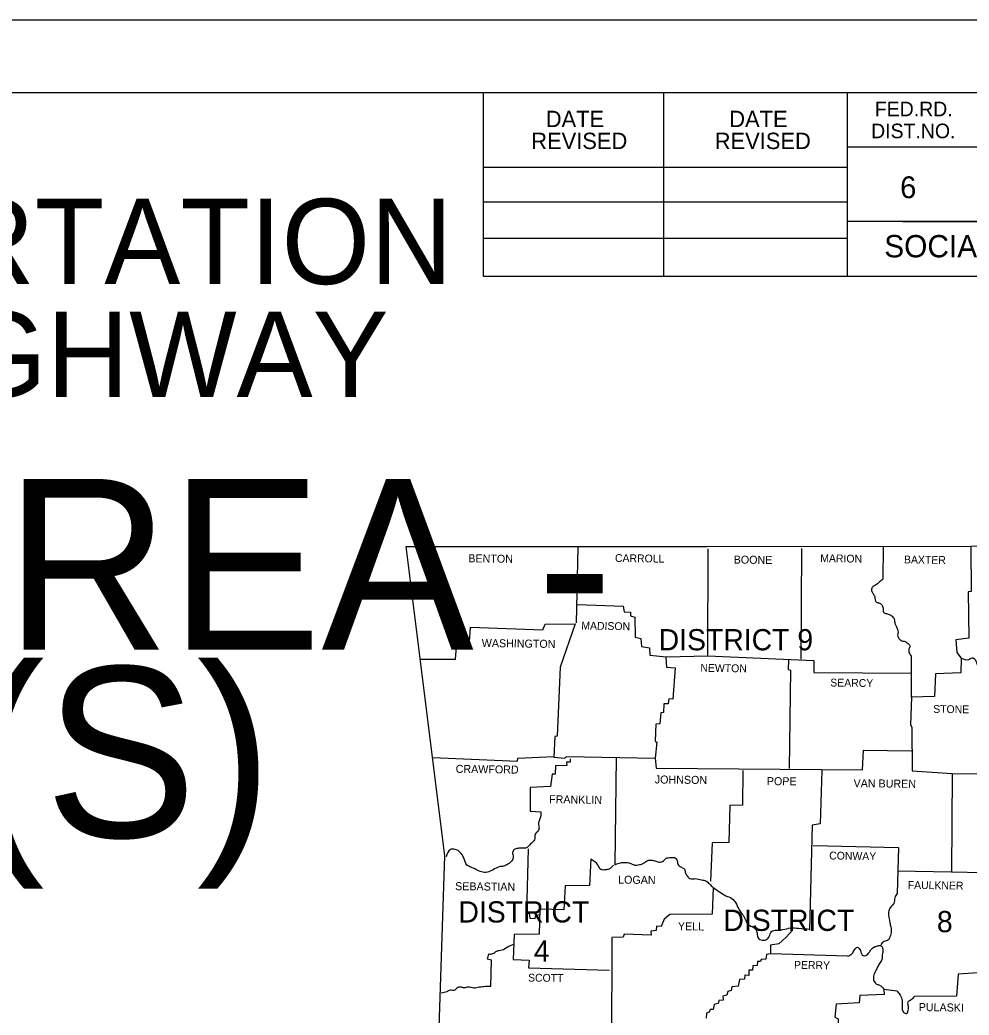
# Model space of a CAD drawing. Extents: x 22866 to 28196, y 1324810 to 1328105.
# Drawn here: x 26170 to 26680, y 1327007 to 1327542 of the extents above; entities that cross this region are included whole.
import ezdxf

# ---------------------------------------------------------------- set-up
doc = ezdxf.new("R2010")
doc.units = 0
for name, color, linetype in [('R_Border', 7, 'Continuous'), ('R_Border Notes', 7, 'Continuous'), ('R_Draft', 7, 'Continuous'), ('R_No Plot', 7, 'Continuous')]:
    doc.layers.add(name, color=color, linetype=linetype)

msp = doc.modelspace()

# ---------------------------------------------------------------- linework, layer by layer
at = {"layer": 'R_Border'}
for p, q in [((23883.86, 1327502.95), (27045.59, 1327502.95)), ((26419.2, 1327404.15), (26419.2, 1327502.95)), ((26516, 1327404.15), (26516, 1327502.95)), ((26614.6, 1327502.95), (26614.6, 1327404.15)), ((27045.59, 1327473.55), (26614.6, 1327473.55)), ((26419.2, 1327462.75), (26614.6, 1327462.75)), ((26419.2, 1327444.15), (26614.6, 1327444.15)), ((27045.59, 1327433.55), (26614.6, 1327433.55)), ((26644.2, 1327433.55), (27045.59, 1327433.55)), ((26419.2, 1327424.75), (26614.6, 1327424.75)), ((27045.59, 1327404.15), (26419.2, 1327404.15))]:
    msp.add_line(p, q, dxfattribs=at)
at = {"layer": 'R_Draft'}
for points in [[(26377.45, 1327259.08), (26539.15, 1327258.98), (26681.05, 1327259.28), (26848.45, 1327261.88), (26926.05, 1327263.68)], [(26377.45, 1327259.08), (26398.15, 1327092.88), (26389.15, 1326821.58)], [(26469.75, 1327258.48), (26468.85, 1327217.98)], [(26469.55, 1327227.88), (26494.15, 1327227.08), (26494.75, 1327223.88), (26498.15, 1327223.78), (26498.05, 1327221.78), (26500.45, 1327221.18), (26500.65, 1327210.28), (26503.75, 1327209.58), (26503.95, 1327205.28), (26508.35, 1327204.68), (26508.55, 1327200.68), (26517.25, 1327199.78), (26539.65, 1327200.28), (26539.85, 1327257.78)], [(26589.95, 1327257.98), (26589.65, 1327198.58)], [(26633.95, 1327258.68), (26633.75, 1327241.58)], [(26681.05, 1327258.68), (26681.25, 1327234.88), (26679.55, 1327234.78), (26679.85, 1327209.88), (26672.85, 1327208.88), (26673.45, 1327202.18), (26675.85, 1327199.08), (26675.65, 1327191.18), (26662.05, 1327190.68), (26661.55, 1327178.48), (26649.15, 1327178.08), (26648.55, 1327163.28), (26649.25, 1327162.08), (26649.55, 1327138.48), (26670.95, 1327137.08), (26670.65, 1327084.38), (26687.65, 1327083.88), (26687.65, 1327030.28), (26674.25, 1327029.28), (26673.25, 1327017.48), (26650.75, 1327017.38)], [(26385.35, 1327198.58), (26404.05, 1327198.48), (26404.55, 1327205.08), (26411.45, 1327205.08), (26412.05, 1327215.78), (26451.05, 1327214.38), (26452.25, 1327217.38), (26468.35, 1327217.48), (26460.25, 1327194.28), (26458.65, 1327157.18), (26457.45, 1327157.08), (26456.85, 1327145.88), (26462.75, 1327145.38), (26463.65, 1327146.28), (26511.35, 1327145.38), (26511.85, 1327140.08)], [(26517.05, 1327199.58), (26517.45, 1327194.18), (26522.05, 1327193.88), (26520.85, 1327177.08), (26518.75, 1327177.18), (26518.35, 1327174.48), (26515.95, 1327174.48), (26515.85, 1327169.88), (26514.35, 1327169.78), (26513.85, 1327163.88), (26511.65, 1327163.58), (26511.35, 1327154.58), (26512.35, 1327153.88), (26511.35, 1327145.38)], [(26539.65, 1327200.28), (26596.65, 1327197.88), (26596.55, 1327191.38), (26648.85, 1327190.98)], [(26582.95, 1327198.18), (26582.85, 1327192.98), (26584.15, 1327192.68), (26583.35, 1327139.88)], [(26649.15, 1327178.08), (26649.05, 1327200.58)], [(26511.85, 1327140.08), (26622.85, 1327139.18), (26623.35, 1327149.68), (26649.15, 1327149.38)], [(26391.95, 1327145.78), (26437.45, 1327143.68), (26437.65, 1327145.28), (26456.65, 1327146.18)], [(26465.65, 1327144.98), (26465.65, 1327143.18), (26463.75, 1327143.18), (26463.85, 1327141.38), (26457.75, 1327141.28), (26457.65, 1327136.78), (26455.95, 1327136.78), (26455.05, 1327130.08), (26444.25, 1327129.58), (26444.15, 1327116.88), (26449.95, 1327116.48)], [(26490.35, 1327145.78), (26489.65, 1327088.08)], [(26558.48, 1327138.81), (26558.38, 1327120.11), (26551.48, 1327120.01), (26550.88, 1327100.11), (26542.08, 1327099.81), (26541.08, 1327079.21)], [(26600.84, 1327138.7), (26600.1, 1327110.11), (26595.71, 1327109.37), (26594.24, 1327052.91)], [(26670.95, 1327137.08), (26722.35, 1327136.78), (26726.75, 1327138.88), (26726.45, 1327099.78), (26723.45, 1327098.48), (26720.75, 1327096.18), (26719.85, 1327095.28), (26719.75, 1327084.08), (26687.05, 1327084.08)], [(26443.15, 1327096.68), (26442.15, 1327062.28), (26443.65, 1327061.88), (26443.95, 1327059.48), (26446.95, 1327059.28), (26447.25, 1327060.98), (26449.65, 1327061.38)], [(26596.35, 1327098.48), (26642.05, 1327097.38), (26641.45, 1327072.68)], [(26476.75, 1327091.28), (26476.05, 1327076.98), (26463.05, 1327076.88), (26462.35, 1327063.88), (26449.45, 1327064.18), (26449.05, 1327050.78), (26435.55, 1327050.68), (26435.15, 1327037.28), (26443.65, 1327036.78), (26443.35, 1327032.68), (26486.75, 1327031.48)], [(26641.55, 1327084.78), (26670.65, 1327084.38)], [(26542.45, 1327075.98), (26542.05, 1327061.58), (26519.25, 1327061.48), (26516.25, 1327058.88), (26514.55, 1327054.88), (26512.05, 1327055.08), (26511.95, 1327052.78), (26509.05, 1327052.48), (26509.15, 1327050.38), (26494.65, 1327050.78), (26494.15, 1327049.18), (26488.15, 1327048.98), (26487.95, 1326990.62)], [(26585.35, 1327053.18), (26581.75, 1327049.28), (26577.85, 1327045.58), (26573.35, 1327044.88), (26573.35, 1327040.18), (26571.15, 1327039.88), (26570.75, 1327037.48), (26568.25, 1327037.28), (26568.05, 1327036.18), (26566.35, 1327036.08), (26566.25, 1327033.98), (26563.85, 1327033.88), (26563.65, 1327031.48), (26561.65, 1327031.48), (26561.75, 1327028.68), (26559.55, 1327028.88), (26559.45, 1327026.68), (26556.75, 1327026.48), (26555.95, 1327022.88), (26552.55, 1327022.58), (26552.25, 1327020.58), (26550.45, 1327020.08), (26549.95, 1327017.98), (26547.65, 1327017.48), (26547.85, 1327015.38), (26545.55, 1327015.18), (26545.15, 1327013.58), (26543.05, 1327012.98), (26542.55, 1327010.28), (26540.95, 1327010.38), (26540.45, 1327008.98), (26538.95, 1327008.48), (26538.85, 1327005.78)], [(26423.05, 1327022.78), (26423.35, 1327036.88), (26421.35, 1327037.48), (26421.95, 1327040.18)], [(26614.65, 1327038.98), (26573.45, 1327040.28)], [(26641.35, 1327020.28), (26634.15, 1327021.08), (26634.45, 1327018.38), (26621.35, 1327017.88), (26620.95, 1327013.98), (26608.65, 1327013.28), (26607.95, 1327006.28), (26609.75, 1327005.38), (26609.75, 1327000.78)]]:
    msp.add_lwpolyline(points, dxfattribs=at)
for points in [[(26633.75, 1327241.58), (26631.95, 1327240.08), (26630.35, 1327238.68), (26627.95, 1327236.98), (26627.65, 1327235.38), (26628.45, 1327233.78), (26629.25, 1327232.48), (26629.55, 1327230.68), (26630.25, 1327229.18), (26631.95, 1327228.58), (26633.35, 1327227.28), (26633.85, 1327225.48), (26634.05, 1327223.78), (26635.65, 1327222.98), (26637.45, 1327222.38), (26639.15, 1327221.18), (26639.95, 1327219.68), (26640.15, 1327217.78), (26640.85, 1327216.28), (26641.65, 1327214.48), (26641.85, 1327212.98), (26641.65, 1327211.48), (26642.05, 1327210.08), (26643.35, 1327208.68), (26645.65, 1327207.98), (26647.25, 1327206.98), (26648.35, 1327205.58), (26647.65, 1327203.88), (26647.75, 1327202.38), (26648.65, 1327200.58)], [(26675.85, 1327199.08), (26679.85, 1327198.38), (26682.25, 1327199.28), (26683.95, 1327196.68), (26684.85, 1327194.68), (26686.35, 1327191.78), (26688.75, 1327190.88), (26690.55, 1327189.28), (26690.55, 1327187.58), (26688.95, 1327185.98), (26687.75, 1327184.38), (26688.15, 1327182.48), (26688.55, 1327179.88), (26688.55, 1327177.38), (26687.95, 1327175.08), (26687.45, 1327172.98), (26687.95, 1327171.18), (26689.85, 1327171.48), (26691.85, 1327172.98), (26693.95, 1327172.98), (26695.95, 1327171.88), (26698.05, 1327169.98), (26700.15, 1327170.38), (26701.85, 1327170.88), (26704.25, 1327171.58), (26705.95, 1327170.68), (26707.45, 1327169.48), (26709.25, 1327167.58), (26710.95, 1327166.38), (26713.15, 1327165.28), (26715.85, 1327164.58), (26718.35, 1327162.88), (26718.75, 1327159.98), (26718.65, 1327157.48), (26718.45, 1327154.38), (26718.25, 1327150.98), (26718.55, 1327147.68), (26719.65, 1327145.48), (26721.05, 1327142.88), (26721.45, 1327140.48), (26721.35, 1327136.68)], [(26449.95, 1327116.48), (26449.95, 1327114.38), (26449.15, 1327112.18), (26448.65, 1327110.28), (26448.95, 1327107.78), (26448.05, 1327105.78), (26446.75, 1327104.18), (26446.75, 1327102.18), (26445.25, 1327100.08), (26443.65, 1327098.48), (26442.25, 1327097.18), (26439.75, 1327096.98), (26437.65, 1327096.88), (26435.55, 1327096.18), (26434.75, 1327094.68), (26435.15, 1327092.38), (26434.35, 1327090.18), (26432.25, 1327088.48), (26429.95, 1327087.38), (26427.55, 1327086.98), (26424.25, 1327085.38), (26421.25, 1327084.08), (26418.05, 1327084.28), (26415.05, 1327085.58), (26412.35, 1327086.78), (26410.25, 1327087.98), (26408.55, 1327091.68), (26407.45, 1327093.68), (26405.55, 1327095.68), (26403.25, 1327096.48), (26401.35, 1327096.28), (26399.05, 1327092.38)], [(26476.75, 1327091.28), (26478.95, 1327089.88), (26480.65, 1327087.58), (26482.15, 1327085.68), (26484.65, 1327085.58), (26486.65, 1327085.98), (26488.95, 1327087.98)], [(26489.65, 1327088.08), (26492.95, 1327089.18), (26495.35, 1327089.38), (26497.75, 1327088.98), (26500.25, 1327087.98), (26502.95, 1327088.18), (26504.95, 1327088.88), (26506.95, 1327090.18), (26509.15, 1327090.58), (26511.25, 1327090.18), (26513.45, 1327089.58), (26515.85, 1327090.28), (26517.25, 1327091.58), (26519.65, 1327091.98), (26521.75, 1327091.98), (26523.25, 1327090.28), (26523.55, 1327088.48), (26525.45, 1327086.78), (26527.15, 1327085.68), (26527.65, 1327083.58), (26528.55, 1327082.08), (26529.45, 1327081.08), (26530.75, 1327080.48), (26532.95, 1327080.68), (26536.35, 1327079.98), (26538.55, 1327079.48), (26540.55, 1327077.78), (26542.45, 1327075.98)], [(26542.45, 1327075.98), (26545.95, 1327073.58), (26549.25, 1327071.48), (26552.65, 1327069.98), (26554.55, 1327067.78), (26556.25, 1327064.38), (26557.65, 1327062.28), (26559.45, 1327059.68), (26560.75, 1327056.78), (26562.85, 1327055.18), (26565.05, 1327053.78), (26566.15, 1327051.28), (26566.65, 1327048.78), (26569.05, 1327047.58), (26571.35, 1327048.08), (26572.65, 1327049.58), (26573.85, 1327052.18), (26576.55, 1327052.98), (26580.05, 1327053.28), (26584.05, 1327054.18), (26588.45, 1327053.98), (26594.65, 1327053.58)], [(26641.45, 1327072.68), (26640.15, 1327070.38), (26639.55, 1327067.38), (26637.95, 1327065.48), (26636.95, 1327063.28), (26636.85, 1327060.38), (26637.35, 1327057.78), (26637.85, 1327055.28), (26638.25, 1327052.98), (26637.75, 1327050.08), (26636.45, 1327047.58), (26634.45, 1327046.88), (26632.55, 1327045.18)], [(26421.95, 1327040.18), (26424.15, 1327040.38), (26426.25, 1327041.78), (26429.05, 1327042.38), (26431.85, 1327043.88), (26435.35, 1327045.48)], [(26614.65, 1327038.98), (26617.15, 1327040.38), (26618.45, 1327042.48), (26620.05, 1327043.78), (26621.65, 1327041.98), (26623.05, 1327039.38), (26624.55, 1327039.38), (26626.45, 1327041.18), (26627.65, 1327042.78), (26629.15, 1327043.98), (26630.75, 1327044.48), (26632.45, 1327044.68), (26633.75, 1327042.78), (26633.35, 1327039.78), (26633.35, 1327037.78), (26632.25, 1327035.68), (26631.05, 1327033.48), (26629.75, 1327030.98), (26628.75, 1327028.28), (26628.95, 1327025.68), (26630.35, 1327023.98), (26631.95, 1327023.48), (26634.15, 1327021.28)], [(26423.05, 1327022.78), (26420.15, 1327022.68), (26416.85, 1327022.28), (26413.85, 1327021.88), (26411.15, 1327022.38), (26408.65, 1327021.98), (26406.95, 1327022.38), (26404.85, 1327021.88), (26403.65, 1327020.68), (26401.15, 1327020.68), (26399.35, 1327019.88), (26396.45, 1327019.18)], [(26641.35, 1327020.28), (26643.05, 1327018.08), (26644.05, 1327015.08), (26644.05, 1327011.68), (26644.85, 1327008.88), (26646.45, 1327008.28), (26647.45, 1327010.68), (26647.25, 1327013.08), (26647.25, 1327014.48), (26648.95, 1327015.68), (26650.75, 1327017.38)]]:
    msp.add_spline(points, degree=3, dxfattribs=at)
at = {"layer": 'R_No Plot'}
msp.add_line((23759.85, 1327541.9), (27093.11, 1327541.9), dxfattribs=at)
msp.add_lwpolyline([(23759.79, 1327541.9), (27093.11, 1327541.9), (27093.11, 1325408.57), (23759.79, 1325408.57)], close=True, dxfattribs=at)

# ---------------------------------------------------------------- texts
at = {"layer": 'R_Border'}
for s, height, p in [('FED.RD.', 7.819, (26629.4, 1327490.15)), ('DATE', 8.792, (26452.58, 1327484.32)), ('DATE', 8.792, (26551.18, 1327484.32)), ('DIST.NO.', 7.819, (26627.4, 1327478.35)), ('REVISED', 8.792, (26444.78, 1327472.52)), ('REVISED', 8.792, (26543.38, 1327472.52)), ('6', 11.72, (26643, 1327446.15))]:
    msp.add_text(s, height=height, dxfattribs=at).set_placement(p)
at = {"layer": 'R_Border Notes'}
msp.add_text('SOCIAL HILL REST AREA - OUACHITA RIVER (S)', height=11.9997, dxfattribs=at).set_placement((26634.45, 1327414.35))
at = {"layer": 'R_Draft'}
for s, height, p in [('ARKANSAS DEPARTMENT OF TRANSPORTATION', 45.7826, (24946.57, 1327400.04)), ('CONSTRUCTION PLANS FOR STATE HIGHWAY', 45.7826, (24987.15, 1327339.43)), ('SOCIAL HILL REST AREA -', 91.598, (24943.49, 1327203.72)), ('DISTRICT 9', 11.4, (26513.25, 1327203.28)), ('OUACHITA RIVER (S)', 91.598, (25067.24, 1327102.84)), ('DISTRICT', 11.4, (26405.65, 1327057.08)), ('DISTRICT', 11.4, (26548.05, 1327052.58)), ('8', 11.4, (26662.75, 1327051.88)), ('4', 11.4, (26446.15, 1327036.08))]:
    msp.add_text(s, height=height, dxfattribs=at).set_placement(p)
for s, height, rotation, p in [('BENTON', 4.301, 359.2527, (26410.95, 1327250.58)), ('CARROLL', 4.201, 359.1481, (26489.75, 1327250.78)), ('MARION', 4.201, 359.1854, (26600.05, 1327250.68)), ('BOONE', 4.301, 359.4001, (26553.55, 1327249.88)), ('BAXTER', 4.201, 359.2559, (26645.05, 1327249.98)), ('MADISON', 4.201, 359.0906, (26471.65, 1327214.48)), ('WASHINGTON', 4.3, 359.232, (26418.15, 1327205.08)), ('NEWTON', 4.201, 359.2717, (26535.65, 1327191.78)), ('SEARCY', 4.199, 359.2527, (26605.45, 1327183.88)), ('STONE', 4.199, 359.4001, (26660.75, 1327169.68)), ('CRAWFORD', 4.299, 359.2771, (26404.15, 1327137.48)), ('JOHNSON', 4.301, 359.3514, (26511.15, 1327131.78)), ('POPE', 4.301, 359.6155, (26571.35, 1327130.88)), ('VAN BUREN', 4.301, 359.3508, (26617.95, 1327129.78)), ('FRANKLIN', 4.301, 359.1815, (26454.35, 1327121.18)), ('CONWAY', 4.199, 359.0371, (26604.85, 1327090.98)), ('SEBASTIAN', 4.299, 359.2816, (26403.85, 1327074.48)), ('LOGAN', 4.301, 359.3969, (26491.45, 1327077.98)), ('FAULKNER', 4.201, 359.2486, (26647.05, 1327075.18)), ('YELL', 4.301, 359.1987, (26523.55, 1327052.98)), ('PERRY', 4.2, 359.0858, (26585.95, 1327032.28)), ('SCOTT', 4.201, 359.4063, (26443.05, 1327025.38)), ('PULASKI', 4.301, 359.053, (26652.95, 1327009.58))]:
    msp.add_text(s, height=height, rotation=rotation, dxfattribs=at).set_placement(p)

doc.saveas('drawing.dxf')
